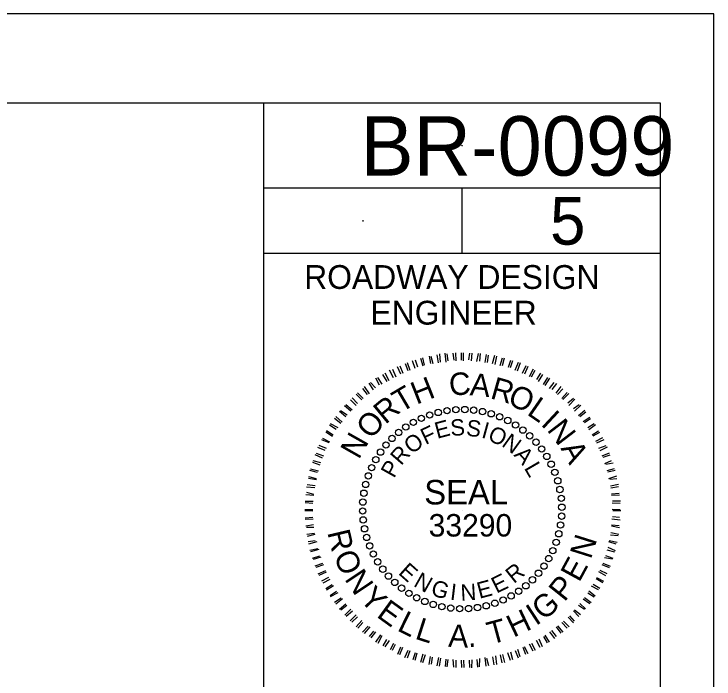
# Model space of a CAD drawing. Extents: x -0.56 to 3.44, y 0 to 1.83.
# Drawn here: x 2.5391 to 2.8333, y 1.5538 to 1.8333 of the extents above; entities that cross this region are included whole.
import ezdxf

# ---------------------------------------------------------------- set-up
doc = ezdxf.new("R2010")
doc.units = 0
for name, color, linetype in [('Default', 7, 'Continuous'), ('Scratch_Level_0', 7, 'Continuous'), ('Sheet PE Seal Cell', 7, 'Continuous'), ('Sheet_Plan_CELL', 7, 'Continuous'), ('Sheet_Title_Block_Text', 7, 'Continuous')]:
    doc.layers.add(name, color=color, linetype=linetype)

msp = doc.modelspace()

# ---------------------------------------------------------------- linework, layer by layer
at = {"layer": 'Scratch_Level_0'}
for p, q in [((2.8333, 1.8333), (0, 1.8333)), ((2.8333, 0), (2.8333, 1.8333))]:
    msp.add_line(p, q, dxfattribs=at)
for centre in [(2.72746, 1.77795), (2.68579, 1.74635), (2.76913, 1.74635)]:
    msp.add_circle(centre, 0.0001, dxfattribs=at)
at = {"layer": 'Sheet PE Seal Cell'}
for p, q in [((2.71103, 1.68534), (2.71017, 1.68851)), ((2.71084, 1.68877), (2.71147, 1.68571)), ((2.7143, 1.68643), (2.71368, 1.6895)), ((2.71425, 1.68953), (2.71511, 1.68636)), ((2.7175, 1.68672), (2.71698, 1.69002)), ((2.71799, 1.69042), (2.71817, 1.68699)), ((2.7207, 1.68701), (2.72038, 1.69078)), ((2.72108, 1.69048), (2.72148, 1.68751)), ((2.7241, 1.68777), (2.72371, 1.69073)), ((2.72462, 1.6909), (2.72481, 1.68746)), ((2.7272, 1.68782), (2.72715, 1.69092)), ((2.72795, 1.69085), (2.7279, 1.68752)), ((2.7303, 1.68788), (2.73071, 1.69077)), ((2.73152, 1.6907), (2.73124, 1.68747)), ((2.73366, 1.68725), (2.73428, 1.69062)), ((2.73509, 1.69055), (2.7348, 1.68732)), ((2.73712, 1.68687), (2.73775, 1.69023)), ((2.73845, 1.68993), (2.73793, 1.6868)), ((2.74025, 1.68635), (2.74121, 1.68985)), ((2.74192, 1.68954), (2.74119, 1.68594)), ((2.74351, 1.68549), (2.74437, 1.68875)), ((2.74518, 1.68868), (2.74432, 1.68542)), ((2.70483, 1.68328), (2.70363, 1.68631)), ((2.70441, 1.68682), (2.7055, 1.68355)), ((2.70776, 1.68424), (2.70666, 1.68751)), ((2.70768, 1.68791), (2.70864, 1.68498)), ((2.74688, 1.68487), (2.74787, 1.68779)), ((2.74857, 1.68749), (2.74758, 1.68456)), ((2.7497, 1.68365), (2.75113, 1.68694)), ((2.75183, 1.68663), (2.75064, 1.68324)), ((2.69855, 1.68041), (2.69689, 1.68365)), ((2.69813, 1.68395), (2.69956, 1.68081)), ((2.70169, 1.68185), (2.70026, 1.68498)), ((2.70127, 1.68538), (2.70247, 1.68235)), ((2.75276, 1.68232), (2.75442, 1.68551)), ((2.75513, 1.6852), (2.7537, 1.68191)), ((2.75581, 1.68099), (2.75748, 1.68418)), ((2.75798, 1.68341), (2.75652, 1.68069)), ((2.69275, 1.67734), (2.69121, 1.68025)), ((2.69189, 1.68051), (2.69376, 1.67774)), ((2.69589, 1.67878), (2.69412, 1.68178)), ((2.69499, 1.68252), (2.69666, 1.67928)), ((2.75887, 1.67967), (2.76057, 1.68228)), ((2.76117, 1.68174), (2.75937, 1.67889)), ((2.76162, 1.67763), (2.76342, 1.68049)), ((2.76412, 1.68018), (2.76222, 1.67709)), ((2.68635, 1.67677), (2.68836, 1.67366)), ((2.69022, 1.67537), (2.68834, 1.67814)), ((2.68902, 1.6784), (2.69109, 1.67611)), ((2.76424, 1.67594), (2.76617, 1.67845)), ((2.76711, 1.67805), (2.76518, 1.67553)), ((2.68351, 1.67409), (2.68582, 1.67169)), ((2.68768, 1.67339), (2.68571, 1.67593)), ((2.76699, 1.67391), (2.76902, 1.67666)), ((2.76976, 1.67578), (2.76759, 1.67336)), ((2.7694, 1.67174), (2.77157, 1.67415)), ((2.77227, 1.67385), (2.76977, 1.6713)), ((2.68288, 1.66877), (2.68057, 1.67117)), ((2.68121, 1.67201), (2.68352, 1.66961)), ((2.68528, 1.67108), (2.68297, 1.67348)), ((2.77192, 1.66981), (2.77422, 1.67189)), ((2.77482, 1.67135), (2.77232, 1.6688)), ((2.68072, 1.66636), (2.67807, 1.66863)), ((2.67861, 1.66923), (2.68126, 1.66696)), ((2.77423, 1.66741), (2.77666, 1.66915)), ((2.77737, 1.66884), (2.77463, 1.6664)), ((2.67855, 1.66394), (2.6759, 1.66621)), ((2.67634, 1.66658), (2.67919, 1.66478)), ((2.77634, 1.66454), (2.77897, 1.66675)), ((2.77948, 1.66597), (2.77694, 1.664)), ((2.67652, 1.66119), (2.67377, 1.66323)), ((2.67441, 1.66406), (2.67706, 1.6618)), ((2.77831, 1.66201), (2.78108, 1.66388)), ((2.78135, 1.6632), (2.77892, 1.66146)), ((2.67459, 1.65868), (2.67173, 1.66047)), ((2.67204, 1.66118), (2.67523, 1.65952)), ((2.78029, 1.65947), (2.78295, 1.66111)), ((2.78356, 1.66057), (2.78069, 1.65846)), ((2.67303, 1.65572), (2.67017, 1.65752)), ((2.67048, 1.65823), (2.67333, 1.65643)), ((2.78206, 1.65647), (2.78472, 1.65811)), ((2.78523, 1.65733), (2.78232, 1.65579)), ((2.67157, 1.653), (2.66851, 1.65433)), ((2.66882, 1.65504), (2.67177, 1.65347)), ((2.78369, 1.6538), (2.7866, 1.65534)), ((2.787, 1.65432), (2.78386, 1.65289)), ((2.6699, 1.64981), (2.66684, 1.65114)), ((2.66725, 1.65208), (2.67031, 1.65075)), ((2.78489, 1.65077), (2.78793, 1.65196)), ((2.78843, 1.65119), (2.78529, 1.64975)), ((2.66881, 1.64665), (2.66575, 1.64798)), ((2.66606, 1.64869), (2.66922, 1.64759)), ((2.78633, 1.64763), (2.78936, 1.64883)), ((2.78952, 1.64792), (2.78659, 1.64695)), ((2.66782, 1.64373), (2.66466, 1.64482)), ((2.66473, 1.64563), (2.66799, 1.64477)), ((2.78742, 1.64436), (2.79022, 1.64566)), ((2.79086, 1.64455), (2.78779, 1.64392)), ((2.66377, 1.64213), (2.66704, 1.64128)), ((2.78838, 1.64143), (2.79155, 1.64229)), ((2.66292, 1.63887), (2.66618, 1.63801)), ((2.66673, 1.64057), (2.66347, 1.64143)), ((2.79172, 1.64138), (2.78865, 1.64075)), ((2.78914, 1.63802), (2.79241, 1.63912)), ((2.66621, 1.63744), (2.66285, 1.63806)), ((2.79247, 1.63797), (2.78951, 1.63758)), ((2.78977, 1.63496), (2.79317, 1.63572)), ((2.66559, 1.63408), (2.66212, 1.63447)), ((2.6623, 1.63551), (2.66576, 1.63512)), ((2.79323, 1.63457), (2.78993, 1.63405)), ((2.66507, 1.63095), (2.66184, 1.63124)), ((2.66201, 1.63228), (2.66504, 1.63152)), ((2.79365, 1.63103), (2.79022, 1.63085)), ((2.79029, 1.63166), (2.79349, 1.63194)), ((2.66468, 1.62749), (2.66145, 1.62777)), ((2.66152, 1.62858), (2.66486, 1.62853)), ((2.79384, 1.6276), (2.79051, 1.62765)), ((2.79068, 1.62869), (2.79401, 1.62864)), ((2.66137, 1.62501), (2.66471, 1.62496)), ((2.66474, 1.62439), (2.6614, 1.62444)), ((2.72775, 1.62471), (2.72775, 1.62471)), ((2.79053, 1.62512), (2.79386, 1.62508)), ((2.79413, 1.6244), (2.7908, 1.62445)), ((2.66492, 1.62095), (2.66149, 1.62077)), ((2.66156, 1.62158), (2.66476, 1.62186)), ((2.79388, 1.6206), (2.79041, 1.62098)), ((2.79058, 1.62203), (2.79358, 1.62185)), ((2.66175, 1.61814), (2.66505, 1.61867)), ((2.7902, 1.61856), (2.79343, 1.61828)), ((2.79359, 1.61737), (2.79023, 1.61799)), ((2.66511, 1.61752), (2.66201, 1.61747)), ((2.66217, 1.61461), (2.66547, 1.61513)), ((2.78991, 1.61533), (2.79328, 1.61471)), ((2.6655, 1.61456), (2.66233, 1.6137)), ((2.79297, 1.61401), (2.78974, 1.61429)), ((2.66279, 1.61154), (2.66576, 1.61193)), ((2.66636, 1.61139), (2.66285, 1.61039)), ((2.78864, 1.60918), (2.7917, 1.60785)), ((2.79225, 1.61041), (2.78909, 1.6115)), ((2.78929, 1.61197), (2.79266, 1.61135)), ((2.66345, 1.6079), (2.66685, 1.60866)), ((2.66722, 1.60822), (2.66371, 1.60723)), ((2.79163, 1.60704), (2.78836, 1.6079)), ((2.66454, 1.60463), (2.66771, 1.60549)), ((2.66808, 1.60505), (2.66481, 1.60396)), ((2.79064, 1.60412), (2.78727, 1.60474)), ((2.78768, 1.60568), (2.79084, 1.60459)), ((2.66564, 1.60136), (2.66891, 1.60246)), ((2.66918, 1.60178), (2.66591, 1.60069)), ((2.78934, 1.60049), (2.78628, 1.60182)), ((2.78659, 1.60252), (2.78965, 1.6012)), ((2.66697, 1.59799), (2.67011, 1.59942)), ((2.67037, 1.59875), (2.66724, 1.59731)), ((2.78791, 1.5972), (2.78496, 1.59876)), ((2.78526, 1.59947), (2.78832, 1.59814)), ((2.66851, 1.59509), (2.67141, 1.59662)), ((2.67181, 1.59561), (2.66891, 1.59407)), ((2.78658, 1.59414), (2.78373, 1.59594)), ((2.78394, 1.59641), (2.78689, 1.59485)), ((2.67017, 1.59185), (2.67284, 1.59348)), ((2.67344, 1.59294), (2.67044, 1.59117)), ((2.78479, 1.59129), (2.78183, 1.59285)), ((2.78248, 1.59369), (2.78533, 1.59189)), ((2.67194, 1.58884), (2.67471, 1.59072)), ((2.67521, 1.58994), (2.67198, 1.58827)), ((2.78289, 1.5882), (2.78027, 1.58989)), ((2.78068, 1.59084), (2.78343, 1.5888)), ((2.67382, 1.58607), (2.67659, 1.58795)), ((2.67719, 1.58741), (2.67432, 1.5853)), ((2.78109, 1.58535), (2.77834, 1.58738)), ((2.77888, 1.58798), (2.78163, 1.58595)), ((2.67592, 1.5832), (2.67856, 1.58541)), ((2.67906, 1.58464), (2.67653, 1.58266)), ((2.67813, 1.58057), (2.68064, 1.58311)), ((2.77468, 1.58282), (2.7772, 1.58089)), ((2.77893, 1.58293), (2.77631, 1.58463)), ((2.77695, 1.58547), (2.77937, 1.5833)), ((2.68137, 1.58224), (2.67874, 1.58003)), ((2.68045, 1.57817), (2.68295, 1.58071)), ((2.68345, 1.57994), (2.68105, 1.57763)), ((2.77429, 1.5774), (2.77198, 1.5798)), ((2.77252, 1.5804), (2.7746, 1.57811)), ((2.77656, 1.58005), (2.77424, 1.58245)), ((2.68299, 1.57566), (2.68526, 1.57831)), ((2.68576, 1.57754), (2.6836, 1.57512)), ((2.77165, 1.57519), (2.76934, 1.57759)), ((2.77012, 1.57809), (2.77243, 1.57569)), ((2.68564, 1.5734), (2.68791, 1.57605)), ((2.68861, 1.57574), (2.68624, 1.57286)), ((2.68849, 1.5716), (2.69032, 1.57388)), ((2.76505, 1.57414), (2.76703, 1.57161)), ((2.76902, 1.57298), (2.76715, 1.57575)), ((2.76758, 1.57612), (2.76979, 1.57348)), ((2.69103, 1.57357), (2.6891, 1.57106)), ((2.69114, 1.56933), (2.69328, 1.57232)), ((2.69365, 1.57188), (2.69198, 1.56869)), ((2.76338, 1.569), (2.76174, 1.57167)), ((2.76228, 1.57227), (2.76405, 1.56927)), ((2.76638, 1.57077), (2.76427, 1.57364)), ((2.69433, 1.56767), (2.69579, 1.57039)), ((2.69673, 1.56998), (2.69504, 1.56736)), ((2.69729, 1.56611), (2.69875, 1.56883)), ((2.69935, 1.56829), (2.69799, 1.5658)), ((2.75737, 1.56546), (2.75583, 1.56836)), ((2.75661, 1.56886), (2.75815, 1.56596)), ((2.76027, 1.567), (2.75874, 1.5699)), ((2.75962, 1.57063), (2.76105, 1.5675)), ((2.70038, 1.56421), (2.7017, 1.56726)), ((2.70241, 1.56696), (2.70108, 1.5639)), ((2.70343, 1.56288), (2.70476, 1.56594)), ((2.70547, 1.56563), (2.70437, 1.56247)), ((2.74774, 1.56517), (2.7486, 1.562)), ((2.7511, 1.56259), (2.7499, 1.56563)), ((2.75078, 1.56637), (2.75164, 1.5632)), ((2.75423, 1.56403), (2.75304, 1.56706)), ((2.75347, 1.56743), (2.75501, 1.56453)), ((2.70693, 1.56192), (2.70792, 1.56485)), ((2.70839, 1.56464), (2.70764, 1.56162)), ((2.71009, 1.56083), (2.71105, 1.56433)), ((2.71199, 1.56392), (2.71079, 1.56052)), ((2.71359, 1.55987), (2.71421, 1.56324)), ((2.71491, 1.56293), (2.71449, 1.56004)), ((2.71695, 1.55925), (2.71767, 1.56285)), ((2.71838, 1.56254), (2.71776, 1.55918)), ((2.72052, 1.5591), (2.7207, 1.56209)), ((2.72151, 1.56202), (2.72099, 1.5589)), ((2.7348, 1.5624), (2.73465, 1.55883)), ((2.73762, 1.55922), (2.73719, 1.56276)), ((2.73767, 1.56256), (2.73853, 1.55939)), ((2.74092, 1.55975), (2.74039, 1.56305)), ((2.74141, 1.56345), (2.74183, 1.55991)), ((2.74432, 1.56051), (2.74356, 1.56391)), ((2.74447, 1.56407), (2.74523, 1.56067)), ((2.74783, 1.5615), (2.74673, 1.56477)), ((2.72398, 1.55871), (2.72369, 1.56191)), ((2.72474, 1.56174), (2.72479, 1.55864)), ((2.72731, 1.55866), (2.72726, 1.56176)), ((2.72807, 1.56169), (2.72812, 1.55859)), ((2.73065, 1.55862), (2.73059, 1.56171)), ((2.7315, 1.56188), (2.73145, 1.55854)), ((2.73408, 1.5588), (2.73379, 1.562))]:
    msp.add_line(p, q, dxfattribs=at)
for centre in [(2.72483, 1.66697), (2.72859, 1.66704), (2.73233, 1.66678), (2.71381, 1.66475), (2.71741, 1.66582), (2.7211, 1.66656), (2.73604, 1.66618), (2.73968, 1.66525), (2.74322, 1.66399), (2.70696, 1.66167), (2.71032, 1.66337), (2.74664, 1.66243), (2.70378, 1.65969), (2.7499, 1.66056), (2.75298, 1.65841), (2.698, 1.6549), (2.70078, 1.65742), (2.75586, 1.65599), (2.69545, 1.65213), (2.7585, 1.65333), (2.69317, 1.64915), (2.7609, 1.65043), (2.69116, 1.64598), (2.76303, 1.64734), (2.76487, 1.64406), (2.68944, 1.64263), (2.76642, 1.64064), (2.68803, 1.63915), (2.68693, 1.63556), (2.76764, 1.63709), (2.68617, 1.63188), (2.76855, 1.63344), (2.76912, 1.62973), (2.68573, 1.62815), (2.76936, 1.62598), (2.68564, 1.62439), (2.68588, 1.62064), (2.76927, 1.62222), (2.68645, 1.61693), (2.76883, 1.61849), (2.76807, 1.61481), (2.68736, 1.61328), (2.76697, 1.61122), (2.68858, 1.60973), (2.76556, 1.60774), (2.69013, 1.60631), (2.69197, 1.60303), (2.76385, 1.60439), (2.6941, 1.59994), (2.76184, 1.60122), (2.6965, 1.59704), (2.75955, 1.59824), (2.69914, 1.59438), (2.757, 1.59547), (2.70202, 1.59196), (2.75123, 1.59068), (2.75422, 1.59295), (2.7051, 1.58981), (2.70836, 1.58794), (2.74804, 1.5887), (2.71178, 1.58638), (2.71532, 1.58513), (2.73759, 1.58455), (2.74119, 1.58562), (2.74468, 1.587), (2.71896, 1.58419), (2.72267, 1.58359), (2.72641, 1.58333), (2.73017, 1.5834), (2.73391, 1.58381)]:
    msp.add_circle(centre, 0.00134, dxfattribs=at)
at = {"layer": 'Sheet_Plan_CELL'}
for p, q in [((2.81079, 1.7958), (0.06079, 1.7958)), ((2.64409, 0.0375), (2.64413, 1.7958)), ((2.81075, 0.0375), (2.81079, 1.7958)), ((2.81079, 1.7601), (2.64413, 1.7601)), ((2.72746, 1.7326), (2.72746, 1.7601)), ((2.81079, 1.7326), (2.64413, 1.7326))]:
    msp.add_line(p, q, dxfattribs=at)
msp.add_circle((2.64413, 1.7326), 0.0001, dxfattribs=at)

# ---------------------------------------------------------------- texts
at = {"layer": 'Default'}
for s, height, p in [('ROADWAY DESIGN', 0.0100002, (2.6611, 1.71775)), ('ENGINEER', 0.01, (2.68896, 1.70275))]:
    msp.add_text(s, height=height, dxfattribs=at).set_placement(p)
at = {"layer": 'Sheet PE Seal Cell'}
for s, height, rotation, p in [('C', 0.00945, 4.1195, (2.72227, 1.67283)), ('H', 0.00945, 21.565, (2.70826, 1.66903)), ('A', 0.00945, 354.565, (2.73046, 1.67305)), ('R', 0.00945, 344.0819, (2.73889, 1.67185)), ('T', 0.00945, 30.565, (2.70171, 1.66553)), ('O', 0.00945, 335.0819, (2.74606, 1.66955)), ('R', 0.00945, 39.565, (2.69516, 1.66055)), ('L', 0.00945, 325.3965, (2.7543, 1.66517)), ('O', 0.00945, 49.8402, (2.68929, 1.65416)), ('I', 0.00945, 317.0132, (2.76017, 1.66067)), ('E', 0.00687, 14.9192, (2.71696, 1.6547)), ('S', 0.00687, 4.0038, (2.72274, 1.6559)), ('S', 0.00687, 352.848, (2.72892, 1.65609)), ('N', 0.00945, 307.3965, (2.76283, 1.65846)), ('F', 0.00687, 25.3509, (2.71206, 1.65209)), ('I', 0.00687, 344.6348, (2.73523, 1.65533)), ('O', 0.00687, 335.4243, (2.73779, 1.65435)), ('N', 0.00945, 60.423, (2.68402, 1.64574)), ('O', 0.00687, 37.1291, (2.70625, 1.64804)), ('N', 0.00687, 324.2692, (2.74369, 1.65191)), ('R', 0.00687, 49.0287, (2.70182, 1.64322)), ('A', 0.00687, 312.2371, (2.74893, 1.64779)), ('A', 0.00945, 298.3965, (2.76869, 1.65077)), ('P', 0.00687, 60.739, (2.69887, 1.63786)), ('L', 0.00687, 300.2563, (2.75333, 1.64247)), ('SEAL', 0.010305, 0.0028, (2.71153, 1.62715)), ('33290', 0.009447, 0.0028, (2.71338, 1.61366)), ('R', 0.00945, 283.2452, (2.67077, 1.61544)), ('N', 0.00945, 72.5046, (2.78155, 1.60384)), ('O', 0.00945, 293.5644, (2.67328, 1.60554)), ('E', 0.00945, 61.4898, (2.77665, 1.59409)), ('E', 0.00687, 318.2926, (2.70031, 1.59811)), ('R', 0.00687, 38.711, (2.74918, 1.59365)), ('N', 0.00945, 303.7838, (2.67782, 1.59578)), ('N', 0.00687, 330.7412, (2.70667, 1.59301)), ('E', 0.00687, 26.1459, (2.74189, 1.5896)), ('G', 0.00687, 343.6968, (2.71392, 1.58912)), ('E', 0.00687, 14.8978, (2.73472, 1.58746)), ('P', 0.00945, 51.2741, (2.77045, 1.5859)), ('Y', 0.00945, 314.4613, (2.68398, 1.58709)), ('I', 0.00687, 353.2466, (2.72216, 1.58712)), ('N', 0.00687, 3.1977, (2.72696, 1.58667)), ('G', 0.00945, 40.1342, (2.76171, 1.57802)), ('E', 0.00945, 324.1361, (2.69112, 1.58012)), ('H', 0.00945, 25.3568, (2.74905, 1.57107)), ('I', 0.00945, 33.2125, (2.75841, 1.57595)), ('L', 0.00945, 333.9963, (2.69974, 1.5743)), ('L', 0.00945, 342.2461, (2.70726, 1.5708)), ('T', 0.00945, 15.1355, (2.73942, 1.56821)), ('A', 0.00945, 357.5853, (2.72149, 1.56733)), ('.', 0.00945, 3.2238, (2.73002, 1.56716))]:
    msp.add_text(s, height=height, rotation=rotation, dxfattribs=at).set_placement(p)
at = {"layer": 'Sheet_Title_Block_Text'}
for s, height, p in [('BR-0099', 0.025, (2.68476, 1.76535)), ('5', 0.02, (2.76439, 1.73635))]:
    msp.add_text(s, height=height, dxfattribs=at).set_placement(p)

doc.saveas('drawing.dxf')
